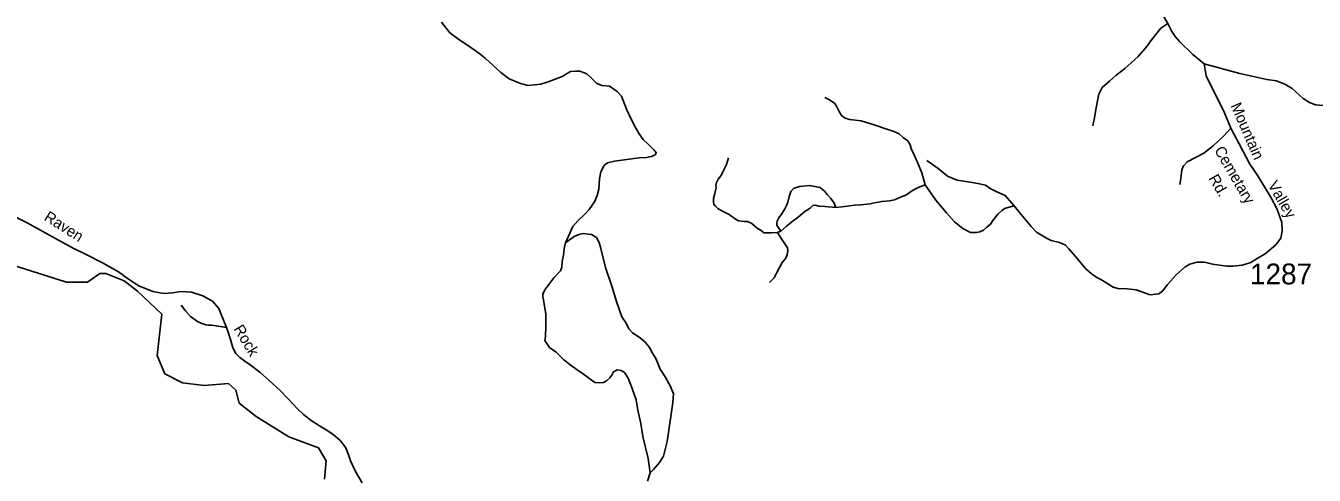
# Model space of a CAD drawing. Extents: x 884530 to 1028605, y 526725 to 653634.
# Drawn here: x 949435 to 957143, y 549998 to 552684 of the extents above; entities that cross this region are included whole.
import ezdxf

# ---------------------------------------------------------------- set-up
doc = ezdxf.new("R2010")
doc.units = 0
for name, color, linetype in [('Exist Hydrographic Creek Single Shore', 7, 'Continuous'), ('Exist Road Non-System Type 51', 7, 'Continuous'), ('Exist Road Non-System Type 51 Label', 7, 'Continuous'), ('Exist Road Secondary Type 51 Attributed', 7, 'Continuous'), ('Exist Road Secondary Type 51 Label', 7, 'Continuous'), ('Exist Road Secondary Type 51 Number Label', 7, 'Continuous')]:
    doc.layers.add(name, color=color, linetype=linetype)

msp = doc.modelspace()

# ---------------------------------------------------------------- linework, layer by layer
at = {"layer": 'Exist Hydrographic Creek Single Shore'}
msp.add_lwpolyline([(951222.8, 549974.7), (951230.9, 550084.2), (951186.3, 550161.2), (951007.9, 550226.1), (950813.3, 550347.8), (950712, 550428.9), (950691.7, 550505.9), (950647.1, 550546.5), (950501.2, 550534.3), (950371.5, 550550.5), (950266, 550603.3), (950221.5, 550712.7), (950247.9, 550960.6), (950103.9, 551098), (950022.8, 551158.8), (949913.4, 551203.4), (949876.9, 551203.4), (949803.9, 551150.7), (949678.2, 551150.7), (949308.1, 551268.4)], dxfattribs=at)
at = {"layer": 'Exist Road Non-System Type 51'}
msp.add_line((953951.1, 551456.6), (953931.8, 551448.1), dxfattribs=at)
for points in [[(952662.8, 551387), (952708.3, 551484), (952738.5, 551520.3), (952779.4, 551558.2), (952805.2, 551587), (952836.2, 551631.7), (952852.9, 551669.6), (952862, 551707.5), (952866.5, 551769.6), (952874.1, 551812), (952895.3, 551848.4), (952915, 551865), (952957.4, 551874.1), (953103.5, 551894.6), (953147.4, 551897.6), (953177.7, 551902.1), (953201.9, 551914.3), (953206.5, 551926.4), (953191.3, 551943.1), (953158, 551976.4), (953127.7, 552005.2), (953103.5, 552038.5), (953082.3, 552076.4), (953058.1, 552121.8), (953027.8, 552185.5), (952999, 552264.3), (952972.5, 552292.3), (952927.1, 552322.6), (952880.1, 552327.1), (952848.3, 552342.3), (952815, 552375.6), (952790.8, 552396.8), (952748.4, 552413.5), (952724.2, 552413.5), (952693.9, 552410.5), (952643.9, 552381.7), (952560.6, 552348.4), (952515.2, 552334.7), (952441, 552327.1), (952394.1, 552339.3), (952326.7, 552367.3), (952276.7, 552405.2), (952184.3, 552488.5), (952151, 552517.3), (952096.5, 552555.2), (952017.8, 552608.2), (951972.3, 552641.5), (951920.9, 552705.2)], [(956267.2, 552698.2), (956225.6, 552669.8), (956171.8, 552603.4), (956138.6, 552557.8), (956090.1, 552500.1), (956067.7, 552480.4), (956008.9, 552428.8), (955955.7, 552388.1), (955918.5, 552354.1), (955873.6, 552314.7), (955853.9, 552276.3), (955844, 552225.9), (955835.2, 552172.2), (955828.7, 552134), (955818.8, 552085.8)], [(954814.9, 551733.5), (954795.1, 551805.3), (954775.4, 551852.9), (954747.6, 551916.7), (954731.4, 551951.7), (954726, 551973.2), (954711.7, 551995.7), (954686.5, 552015.4), (954659.2, 552038.3), (954627.8, 552052.7), (954580.2, 552067.9), (954516.5, 552089.5), (954432.1, 552115.5), (954363.5, 552124.9), (954337.5, 552132.1), (954315, 552147.4), (954299.8, 552171.6), (954284.5, 552204.8), (954275.5, 552219.2), (954243.7, 552242.1), (954215, 552256.4)], [(956643.8, 552072.9), (956602.5, 552026.2), (956538.8, 551966.9), (956482.3, 551922), (956381.7, 551870.9), (956360.2, 551846.6), (956350.3, 551822.4), (956345.9, 551790.1), (956343.2, 551757.8), (956338.7, 551736.2)], [(953931.8, 551448.1), (953893.2, 551447.2), (953849.3, 551447.2), (953834, 551459.8), (953809.8, 551474.1), (953777.5, 551501.9), (953752.3, 551513.6), (953732.6, 551513.6), (953698.5, 551519), (953680.6, 551528.9), (953642, 551556.7), (953598.9, 551578.2), (953574.7, 551592.6), (953560.3, 551605.2), (953550.4, 551617.7), (953548.2, 551632.6), (953548.2, 551652.3), (953554.5, 551674.7), (953559.9, 551691.8), (953564.3, 551716.9), (953562.5, 551728.6), (953567, 551746.6), (953576.9, 551768.1), (953592.2, 551787.8), (953602, 551805.8), (953613.7, 551827.3), (953626.3, 551855.2), (953638.8, 551894.7)], [(955347.9, 551608.8), (955294.5, 551669.4), (955244.3, 551692.7), (955204.8, 551712.4), (955176.1, 551732.2), (955131.2, 551741.2), (955072, 551751.9), (955007.4, 551760.9), (954948.1, 551786.1), (954892.5, 551830.9), (954824.3, 551879.4)], [(954280.9, 551597.1), (954270.6, 551624.5), (954250.9, 551651.4), (954228.4, 551675.6), (954215.9, 551693.6), (954186.2, 551717.8), (954122.5, 551730.4), (954063.3, 551723.2), (954028.3, 551711.5), (954011.3, 551693.6), (954001.4, 551664), (953994.2, 551629.9), (953986.1, 551610.1), (953976.3, 551590.4), (953959.2, 551563.4), (953939.5, 551535.6), (953929.6, 551515.9), (953928.7, 551504.2), (953928.7, 551491.6), (953951.1, 551456.6)], [(954814.9, 551733.5), (954773.6, 551718.3), (954739.5, 551699.4), (954700, 551672.5), (954667.7, 551659.9), (954630.9, 551642.9), (954601.7, 551638.8), (954555.1, 551634.3), (954512.9, 551626.3), (954486, 551619.1), (954431.2, 551613.7), (954391.8, 551611.9), (954318.6, 551601.6), (954280.9, 551597.1)], [(955347.9, 551608.8), (955296.8, 551593.5), (955274.3, 551580), (955250.1, 551557.6), (955220.5, 551520.8), (955205.2, 551498.4), (955183.7, 551481.3), (955164, 551463.3), (955141.5, 551453.5), (955121.8, 551449), (955086.8, 551449), (955039.7, 551471.9), (954991.2, 551513.2), (954941.9, 551565.2), (954879, 551641.5), (954814.9, 551733.5)], [(950635.4, 550879.7), (950614, 550935), (950588.7, 550993.3), (950551.9, 551037.7), (950494.4, 551070.8), (950426.1, 551091), (950362.6, 551095), (950313.7, 551087.9), (950259, 551083.8), (950194, 551095), (950110.5, 551130.4), (950048.6, 551170.5), (949989.1, 551213.1), (949894.5, 551268.1), (949795.9, 551317.5), (949718.4, 551354.9), (949647.5, 551393.3), (949555.4, 551445.1), (949443.4, 551505.7), (949366.7, 551545.2), (949303.1, 551576.9), (949246.1, 551604.6)], [(954280.9, 551597.1), (954215.9, 551604.7), (954179.1, 551606.5), (954159.3, 551611.9), (954144.1, 551610.1), (954127, 551594.9), (954094.7, 551575.1), (954055.2, 551541), (954018.4, 551511.4), (953986.1, 551486.2), (953951.1, 551456.6)], [(956237.7, 551100.3), (956212.6, 551081.4), (956195.5, 551079.6), (956160.5, 551076.9), (956077.1, 551106.5), (956005.3, 551114.6), (955975.7, 551111.9), (955940.7, 551120.9), (955911.1, 551140.6), (955867.1, 551167.6), (955842, 551180.1), (955807.9, 551202.6), (955775.5, 551232.2), (955714.1, 551304.5), (955674.6, 551351.1), (955654.8, 551373.6), (955618.1, 551388.8), (955568.7, 551400.5), (955540.9, 551414.9), (955482.1, 551451.2), (955448.9, 551485.3), (955379.8, 551568.8), (955347.9, 551608.8)], [(952662.8, 551387), (952715.1, 551425.6), (952748.4, 551439.3), (952774.1, 551442.3), (952798.4, 551439.3), (952819.6, 551436.2), (952849.8, 551418.1), (952865, 551389.3), (952874.1, 551352.9), (952902.8, 551239.3), (952940.7, 551127.2), (952969.5, 551036.2), (953000.5, 550944.6), (953026.3, 550906.7), (953042.9, 550873.4), (953064.1, 550849.1), (953109.5, 550818.8), (953142.9, 550790), (953167.1, 550761.2), (953183.7, 550727.9), (953204.9, 550694.6), (953217.1, 550661.2), (953230.7, 550632.5), (953259.5, 550585.5), (953292, 550527.2), (953308.7, 550484.7), (953305.6, 550431.7), (953293.5, 550348.4), (953272.3, 550198.4), (953250.4, 550111.3), (953226.1, 550073.4), (953189.8, 550030.9), (953170.1, 550012.8)], [(953931.8, 551448.1), (953951.6, 551415.8), (953971.3, 551387), (953991.1, 551356.5), (953994.6, 551339.5), (953989.3, 551317.9), (953982.1, 551295.5), (953959.7, 551268.6), (953928.7, 551209.8), (953911.6, 551178.3), (953884.7, 551148.7)], [(953153.5, 549961.3), (953170.1, 550012.8), (953158.8, 550098.4), (953125.4, 550228.7), (953113.3, 550307.5), (953096.7, 550386.3), (953086.8, 550449.1), (953062.6, 550515.8), (953038.4, 550577.9), (953017.2, 550611.3), (952996, 550623.4), (952971.7, 550627.9), (952950.5, 550615.8), (952941.5, 550596.1), (952929.3, 550579.4), (952908.1, 550562.8), (952891.5, 550552.2), (952867.3, 550549.1), (952838.5, 550552.2), (952808.2, 550573.4), (952771.9, 550602.2), (952734, 550627.9), (952691.6, 550656.7), (952650.7, 550690), (952608.3, 550732.5), (952567.4, 550761.2), (952540.9, 550802.9), (952544, 550827.2), (952545.5, 550889.3), (952545.5, 550960.5), (952531.9, 551046.9), (952528.8, 551063.5), (952528.8, 551080.2), (952539.4, 551105.9), (952593.9, 551177.2), (952634.1, 551220.3), (952641.6, 551241.5), (952643.2, 551274.9), (952650.7, 551312.8), (952655.3, 551353.7), (952662.8, 551387)], [(950635.4, 550879.7), (950574, 550891.1), (950546.7, 550895), (950528, 550894.9), (950511.1, 550896.1), (950487.3, 550903.6), (950461.4, 550916), (950419.5, 550946.4), (950389.3, 550979.8), (950364.9, 551014.6)], [(951448.1, 549952.5), (951406.3, 550020.5), (951376.8, 550083.1), (951365.9, 550119.9), (951348.5, 550160.6), (951316.9, 550202.9), (951272.6, 550242.1), (951232.3, 550268.5), (951191.2, 550292.7), (951142.9, 550325.3), (951096.4, 550361.3), (951059.4, 550394.4), (951032.8, 550423.4), (951000.9, 550458.8), (950957.7, 550502.2), (950889.5, 550566.7), (950835.6, 550614.5), (950777.7, 550657.8), (950745.9, 550679.3), (950715.2, 550701.8), (950691.3, 550724.7), (950674.1, 550758.9), (950662.3, 550803.1), (950643.6, 550858.4), (950635.4, 550879.7)]]:
    msp.add_lwpolyline(points, dxfattribs=at)
at = {"layer": 'Exist Road Secondary Type 51 Attributed'}
for points in [[(956484.1, 552456.1), (956416.7, 552511.8), (956339.6, 552589), (956311, 552620.7), (956291.6, 552649.3), (956267.2, 552698.2), (956230, 552761.8), (956213.1, 552794.2), (956165.9, 552908.1), (956136.3, 552962.9), (956103.3, 553014.2), (956054, 553069), (956013.2, 553109.8), (955976.5, 553152.7), (955964.3, 553175.2), (955942.4, 553223.2), (955939.1, 553270.1), (955939.9, 553306), (955944.1, 553366.2), (955950.4, 553422.6)], [(957810.4, 552677), (957765.5, 552654.5), (957736.1, 552627.9), (957561.2, 552438.9), (957505.3, 552370), (957473.9, 552336.8), (957404.8, 552295.5), (957320.9, 552253.7), (957251.8, 552231.3), (957197.9, 552208.8), (957150.4, 552211.5), (957113.6, 552225), (957076.3, 552248.8), (957009.9, 552308.9), (956967.8, 552335.9), (956916.6, 552355.6), (956859.5, 552363.3), (956697.2, 552398.2), (956484.1, 552456.1)], [(956484.1, 552456.1), (956495.7, 552386.1), (956605.4, 552164.2), (956643.8, 552072.9), (956693.1, 551978.6), (956757.8, 551857.4), (956805.8, 551788.2), (956884.7, 551655.9), (956918.8, 551592.2), (956948.9, 551508.9), (956951.9, 551455.8), (956943.5, 551414.9), (956913.9, 551375.4), (956849.3, 551321.5), (956802.2, 551294), (956762.7, 551269), (956712.4, 551253.7), (956656.8, 551247.5), (956619.1, 551247.5), (956534.8, 551259.1), (956485.4, 551270.8), (956440.1, 551272.1), (956397.9, 551259.6), (956370.1, 551242.5), (956318, 551198.5), (956265.1, 551138.4), (956237.7, 551100.3)]]:
    msp.add_lwpolyline(points, dxfattribs=at)

# ---------------------------------------------------------------- texts
at = {"layer": 'Exist Road Non-System Type 51 Label'}
for s, rotation, p in [('Raven', 327.5321, (949538.8, 551525.7)), ('Rock', 301.01524, (950675.6, 550872.6))]:
    msp.add_text(s, height=65.62, rotation=rotation, dxfattribs=at).set_placement(p)
at = {"layer": 'Exist Road Secondary Type 51 Label'}
for s, rotation, p in [('Mountain', 293.53563, (956641.1, 552207.8)), ('Cemetary', 300.31406, (956543.1, 551941.1)), ('Rd.', 300.31406, (956508.4, 551772.9)), ('Valley', 300.0581, (956862.8, 551733.2))]:
    msp.add_text(s, height=65.62, rotation=rotation, dxfattribs=at).set_placement(p)
at = {"layer": 'Exist Road Secondary Type 51 Number Label'}
msp.add_text('1287', height=125, dxfattribs=at).set_placement((956758.3, 551138.2))

doc.saveas('drawing.dxf')
